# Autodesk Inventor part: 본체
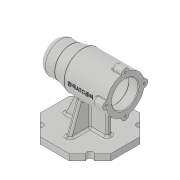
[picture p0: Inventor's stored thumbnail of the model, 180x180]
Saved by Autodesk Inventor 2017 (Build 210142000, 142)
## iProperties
Created: 2019-12
Part Number: 본체
Material: Generic
Document SubType Name: Modeling
Designer: 5-10-le
Density: 1 g/cm^3
Appearance: Default
Author: 5-10-le
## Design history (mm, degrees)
sketch "스케치1"
  geometry: 1 further point
sketch "스케치2"
  geometry: 1 further point
sketch "스케치3"
  geometry: L1 (-23.196, -56)-(-56, -23.196); L2 (-56, -23.196)-(-56, 23.196); L3 (-56, 23.196)-(-23.196, 56); L4 (-23.196, 56)-(23.196, 56); L5 (23.196, 56)-(56, 23.196); L6 (56, 23.196)-(56, -23.196); L7 (56, -23.196)-(23.196, -56); L8 (23.196, -56)-(-23.196, -56); L9 (0, 0)-(71.034, 0); 2 further points
  constraints: 18 end point, 1 horizontal, 1 midpoint, 17 other
extrude "돌출1" new body sketch "스케치3" distance "d2" = 10; taper "d3" = 0 deg
sketch "스케치4"
  geometry: L1 (-23.196, 56)-(-56, 23.196) reference; L2 (0, 0)-(-39.598, 39.598); L3 (0, 0)-(-91.826, 0); L4 (56, 23.196)-(23.196, 56) reference; L5 (-56, -23.196)-(-23.196, -56) reference; L6 (23.196, -56)-(56, -23.196) reference; L7 (39.598, 39.598)-(-39.598, -39.598); L8 (39.598, -39.598)-(0, 0); L9 (0, 0)-(79.196, 0); C1 r 5 at (-39.598, 39.598); C2 r 5 at (39.598, -39.598); C3 r 5 at (-39.598, -39.598); C4 r 5 at (39.598, 39.598); 2 further points
  constraints: 10 end point, 4 centre point, 4 midpoint, 2 coincident, 2 horizontal, 1 collinear, 1 perpendicular, 3 other
  dimensions: "d4" = 10 diameter of C1; "d7" = 10 diameter of C4; "d8" = 10 diameter of C3; "d9" = 10 diameter of C2
extrude "돌출2" cut sketch "스케치4" stored distance "d5" = 10; taper "d6" = 0 deg
sketch "스케치5"
  geometry: L1 (0, 0)-(0, 80); L2 (56, 0)-(56, 10) reference; L3 (56, 0)-(56, 80); L4 (-56, 80)-(56, 80); L5 (-56, 80)-(-56, 105); L6 (-11, 110)-(56, 110); L7 (-31, 105)-(-11, 110); L8 (-56, 105)-(-31, 105); L9 (56, 80)-(56, 110)
  constraints: 16 end point, 4 vertical, 2 parallel, 1 perpendicular
  dimensions: "d10" = 80 distance of L1.start L1.end; "d19" = 60 diameter of L6.start L4; "d20" = 50 diameter of L8 L4; "d21" = 25 distance from line of L7.start L5; "d22" = 45 distance from line of L6.start L5
revolve "회전1" sketch "스케치5" stored, may be unused: angle "d23" = 90 deg
fillet "모깎기1" dims "d24" = 10
sketch "스케치7"
  geometry: C1 r 30 at (0, 0) reference; C2 r 21 at (0, 0); 1 further point
  constraints: 1 centre point, 1 coincident
  dimensions: "d27" = 42 diameter of C2
extrude "돌출3" cut sketch "스케치7" distance "d28" = 15; taper "d29" = 0 deg
sketch "스케치8"
  geometry: C1 r 21 at (0, 0) reference; C2 r 24 at (0, 0); 1 further point
  constraints: 1 centre point, 1 coincident
  dimensions: "d30" = 48 diameter of C2
extrude "돌출4" cut sketch "스케치8" distance "d31" = 54; taper "d32" = 0 deg
sketch "스케치9"
  geometry: C1 r 24 at (0, 0) reference; C2 r 21 at (0, 0); 1 further point
  constraints: 1 centre point, 1 coincident
  dimensions: "d33" = 42 diameter of C2
extrude "돌출5" cut sketch "스케치9" distance "d34" = 12; taper "d35" = 0 deg
sketch "스케치10"
  geometry: C1 r 21 at (0, 0) reference; C2 r 17.5 at (0, 0); 1 further point
  constraints: 1 centre point, 1 coincident
  dimensions: "d36" = 35 diameter of C2
extrude "돌출6" cut sketch "스케치10" distance "d37" = 18; taper "d38" = 0 deg
sketch "스케치11"
  geometry: C1 r 17.5 at (0, 0) reference; C2 r 16 at (0, 0); 1 further point
  constraints: 1 centre point, 1 coincident
  dimensions: "d39" = 32 diameter of C2
extrude "돌출7" cut sketch "스케치11" distance "d40" = 4; taper "d41" = 0 deg
sketch "스케치12"
  geometry: C1 r 16 at (0, 0) reference; C2 r 10.5 at (0, 0); 1 further point
  constraints: 1 centre point, 1 coincident
  dimensions: "d42" = 21 diameter of C2
extrude "돌출8" cut sketch "스케치12" distance "d43" = 3; taper "d44" = 0 deg
sketch "스케치13"
  geometry: 1 further point
fillet "모깎기2" dims "d45" = 3
fillet "모깎기3" dims "d46" = 0.3
fillet "모깎기4" dims "d47" = 3
chamfer "모따기1" distance "d48" = 1; stored, may be unused: second distance "d49" = 2, angle "d50" = 45 deg
sketch "스케치14"
  geometry: C1 r 6 at (0, 30); 2 further points
  constraints: 1 centre point, 1 vertical alignment, 1 other
  dimensions: "d51" = 12 diameter of C1
extrude "돌출9" join sketch "스케치14" distance "d52" = 16; taper "d53" = 0 deg
fillet "모깎기5" dims "d54" = 3
fillet "모깎기6" dims "d55" = 1
sketch "스케치15"
  geometry: A1 r 6 centre (0, 0) between (5.998, 0.171) and (-5.998, 0.171) reference; A2 r 6 centre (-30, -30) between (-30.171, -24.002) and (-30.171, -35.998) reference; A3 r 6 centre (0, -60) between (-5.998, -60.171) and (5.998, -60.171) reference; A4 r 6 centre (30, -30) between (30.171, -35.998) and (30.171, -24.002) reference; 5 further points
  constraints: 4 coincident
hole "구멍1" sketch "스케치15" at (-30, -30), (0, 0), (30, -30), (0, -60) diameter "d59" = 3.242; stored, may be unused: countersink angle "d63" = 90 deg, drill point angle "d65" = 118 deg; dims "d60" = 8, "d61" = 4, "d62" = 2, "d64" = 11
sketch "스케치19"
  geometry: L1 (56, -23.196)-(56, 23.196) reference; L2 (0, -4)-(31, -4); L3 (31, -4)-(31, 4); L4 (31, 4)-(0, 4); L5 (2.576, 0.332)-(31, 4); L6 (31, -4)-(2.576, -0.332); L7 (0, 4)-(0, -4); 1 further point
  constraints: 12 end point, 2 point on line, 1 horizontal, 1 midpoint, 1 parallel, 1 perpendicular
  dimensions: "d77" = 8 distance of L2.end L3.end; "d78" = 25 distance from line of L1 L3.end
extrude "돌출10" join sketch "스케치19" stored distance "d79" = 8; taper "d80" = 0 deg
sketch "스케치20"
  geometry: L1 (-23.196, 10)-(-36.062, 10) reference; L2 (-56, 10)-(-43.134, 10) reference; L3 (-56, 0)-(-56, 10) reference; L4 (-31, 55)-(-11, 50) reference; L5 (-43.134, 10)-(-34.598, 10) reference; L6 (-11, 50)-(39, 50) reference; L7 (-31, 55)-(-31, 105) reference; L8 (-46, 105)-(-46, 55) reference; L9 (-23.196, 10)-(23.196, 10) reference; L10 (-36.062, 10)-(-36.062, 0) reference; L11 (-23.196, 0)-(-36.062, 0) reference; L12 (-23.196, 0)-(-23.196, 10) reference; L13 (-36.062, 10)-(-23.196, 10) reference; L14 (-43.134, 0)-(-43.134, 10) reference; L15 (-56, 10)-(-43.134, 10) reference; L16 (-56, 0)-(-56, 10) reference; L17 (-43.134, 0)-(-56, 0) reference; L18 (-31, 55)-(-11, 50) reference; L19 (-18.476, 51.869)-(-38, 10); L20 (-36.062, 10)-(-23.196, 10) reference; 1 further point
  constraints: 2 end point, 2 point on line
  dimensions: "d113" = 115 deg angle of L2 L19; "d114" = 18 distance from line of L16 L19.end
feature "리브1" sketch "스케치20" dims "d91" = 1, "d92" = 8, "d93" = 0, "d94" = 0, "d95" = 1, "d96" = 1
sketch "스케치21"
  geometry: L1 (10, 43.134)-(10, 34.598) reference; L2 (10, -23.196)-(10, 23.196) reference; L3 (10, 23.196)-(10, 36.062) reference; L4 (10, 43.134)-(10, 56) reference; L5 (56.766, 18.979)-(10, 36); L6 (0, 56)-(10, 56) reference; A1 r 30 centre (80, 0) between (56.766, 18.979) and (50.268, -4) reference; 2 further points
  constraints: 2 end point, 1 point on circle, 1 point on line
  dimensions: "d97" = 20 distance from line of L6 L5.end; "d98" = 110 deg angle of L4 L5
feature "리브2" sketch "스케치21" dims "d99" = 1, "d100" = 8, "d101" = 0, "d102" = 0, "d103" = 1, "d104" = 1
sketch "스케치22"
  geometry: L1 (10, -34.598)-(10, -43.134) reference; L2 (10, -36.062)-(10, -23.196) reference; L3 (10, -23.196)-(10, 23.196) reference; L4 (10, -56)-(10, -43.134) reference; L5 (56.766, -18.979)-(10, -36); L6 (0, -56)-(10, -56) reference; A1 r 30 centre (80, 0) between (56.766, -18.979) and (50.268, -4) reference; 2 further points
  constraints: 2 end point, 1 point on circle, 1 point on line
  dimensions: "d105" = 20 distance from line of L6 L5.end; "d106" = 110 deg angle of L4 L5
feature "리브3" sketch "스케치22" dims "d107" = 1, "d108" = 8, "d109" = 0, "d110" = 0, "d111" = 1, "d112" = 1
fillet "모깎기7" dims "d115" = 3
fillet "모깎기8" dims "d116" = 3
fillet "모깎기9" dims "d117" = 3
fillet "모깎기10" dims "d118" = 3
fillet "모깎기11" dims "d119" = 3
fillet "모깎기12" dims "d120" = 3
fillet "모깎기13" dims "d121" = 3
node "작업 평면1"
sketch "스케치23"
  geometry: L1 (33.5, -29.226)-(20.5, -29.226) reference; L2 (33.5, -6.771)-(33.5, -29.226) reference; L3 (20.5, -6.771)-(33.5, -6.771) reference; L4 (16.5, 2.779)-(16.5, -2.779) reference; L5 (33.5, 6.771)-(20.5, 6.771) reference; L6 (33.5, 29.226)-(33.5, 6.771) reference; L7 (20.5, 29.226)-(33.5, 29.226) reference; L8 (16.5, 29.871)-(16.5, 29.871) reference; L9 (33.5, 29.226)-(20.5, 29.226) reference; L10 (33.5, 6.771)-(33.5, 29.226) reference; L11 (20.5, 6.771)-(33.5, 6.771) reference; L12 (16.5, -2.779)-(16.5, 2.779) reference; L13 (33.5, -6.771)-(20.5, -6.771) reference; L14 (33.5, -29.226)-(33.5, -6.771) reference; L15 (20.5, -29.226)-(33.5, -29.226) reference; L16 (16.5, -29.871)-(16.5, -29.871) reference; L17 (-33.131, -29.31)-(-33.131, -29.31) reference; L18 (-29.5, -29.317)-(-33.131, -29.317) reference; L19 (-29.5, -25.428)-(-29.5, -29.317) reference; L20 (-21.5, -21.945)-(-23.5, -21.945) reference; L21 (-15.5, -29.317)-(-15.5, -25.428) reference; L22 (5.5, -29.317)-(-15.5, -29.317) reference; L23 (11.5, -29.986)-(11.5, -29.986) reference; L24 (-15.5, -29.317)-(5.5, -29.317) reference; L25 (-15.5, -25.428)-(-15.5, -29.317) reference; L26 (-23.5, -21.945)-(-21.5, -21.945) reference; L27 (-29.5, -29.317)-(-29.5, -25.428) reference; L28 (-33.131, -29.317)-(-29.5, -29.317) reference; L29 (-33.131, 30)-(-33.131, -29.31) reference; L30 (-22.5, 0)-(7.5, 0); L31 (0.696, -80)-(-45.696, -80) reference; L32 (-7.5, 0)-(-7.5, 65.359); 1 further point
  constraints: 4 end point, 2 horizontal, 1 midpoint, 1 vertical, 16 other
  dimensions: "d122" = 80 distance between parallel lines of L31 L30; "d123" = 41 distance between parallel lines of L6 L32; "d124" = 30 distance of L30.start L30.end
feature "엠보싱1" sketch "스케치23" dims "d6" = 0, "d125" = 0.5, "d126" = 0
node "솔리드1"
pattern_circular "원형 패턴1" dims angle "d57" = 360 deg
node "투영된 루프1"
node "투영된 루프2"
node "투영된 루프3"
node "투영된 루프4"
other parameters: "sa_0" = 4
